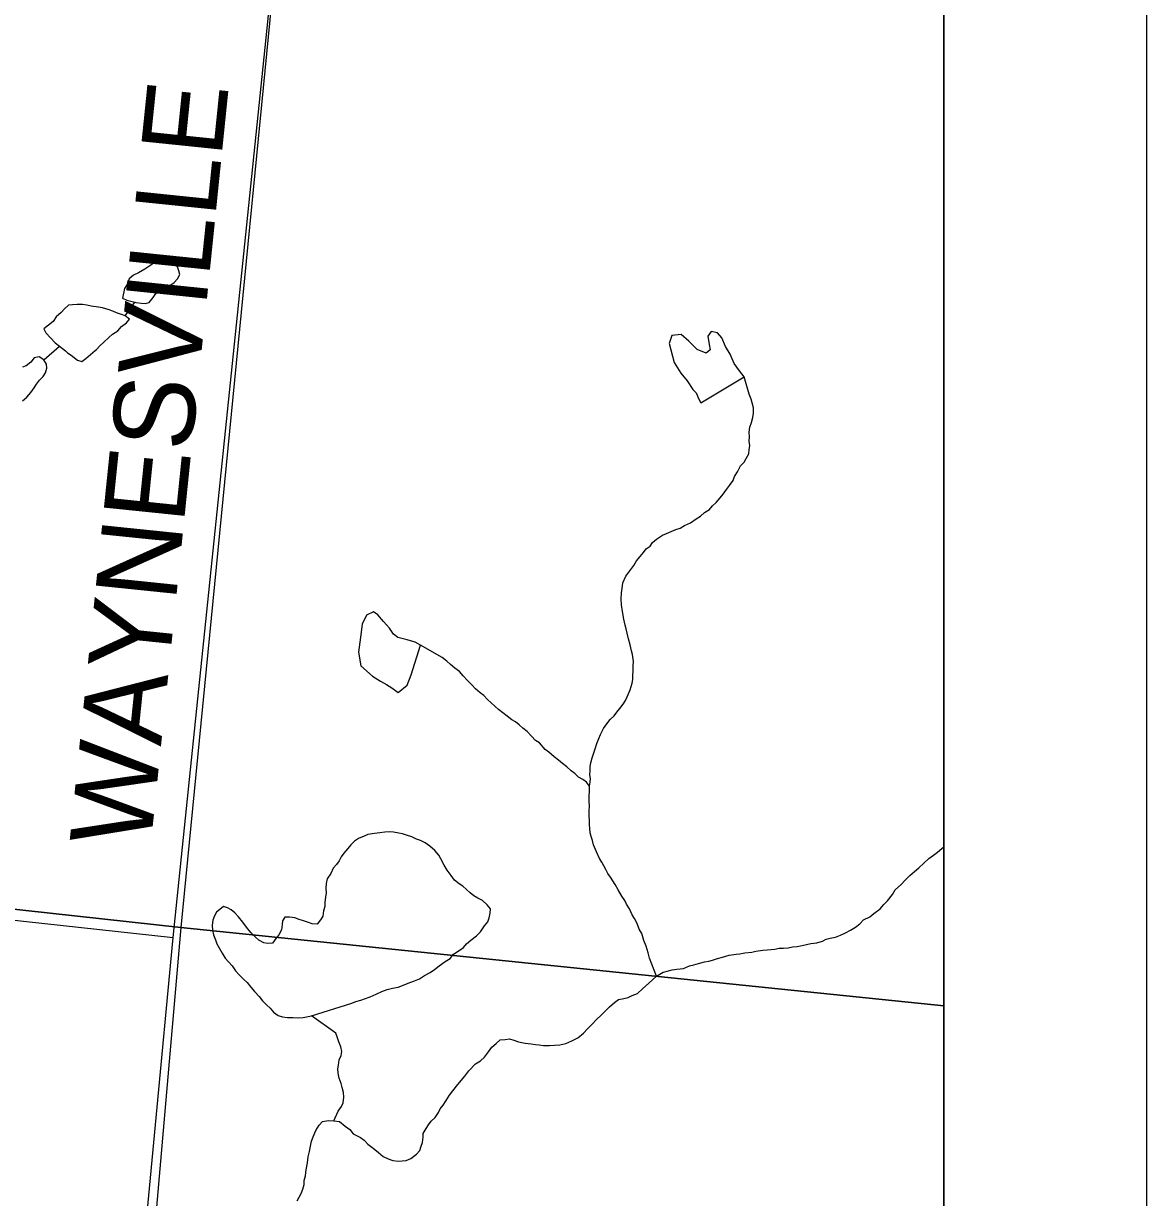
# Model space of a CAD drawing. Extents: x 0 to 34, y -4 to 22.
# Drawn here: x 8.446 to 9, y 18.278 to 18.856 of the extents above; entities that cross this region are included whole.
import ezdxf

# ---------------------------------------------------------------- set-up
doc = ezdxf.new("R2010")
doc.units = 0
for name, color, linetype in [('GM_X_Minor_Lake', 7, 'Continuous'), ('GM_X_Minor_River', 7, 'Continuous'), ('GM_X_Section', 7, 'Continuous'), ('GM_X_Township', 7, 'Continuous'), ('GM_X_Township_Road', 7, 'Continuous'), ('GM_X_Township_Road_Text', 7, 'Continuous'), ('SH_Data', 7, 'Continuous'), ('SN_P_Text', 7, 'Continuous')]:
    doc.layers.add(name, color=color, linetype=linetype)

msp = doc.modelspace()

# ---------------------------------------------------------------- linework, layer by layer
at = {"layer": 'GM_X_Minor_Lake'}
msp.add_line((8.54502, 18.42137), (8.54145, 18.41854), dxfattribs=at)
for points in [[(8.50129, 18.71911), (8.50181, 18.71896), (8.50448, 18.71861), (8.50635, 18.71855), (8.50824, 18.71903), (8.5102, 18.72137), (8.51161, 18.72347), (8.51381, 18.72527), (8.51572, 18.72628), (8.51843, 18.72726), (8.52062, 18.7288), (8.52229, 18.73062), (8.52343, 18.73272), (8.52296, 18.7346), (8.52222, 18.7365), (8.52042, 18.73896), (8.51891, 18.74168), (8.5165, 18.74175), (8.5146, 18.74101), (8.51159, 18.73923), (8.50912, 18.73744), (8.50611, 18.73539), (8.5031, 18.73361), (8.50065, 18.73236), (8.49845, 18.73055), (8.49756, 18.72818), (8.49615, 18.72582), (8.49518, 18.72104)], [(8.49518, 18.72104), (8.4973, 18.72017), (8.50129, 18.71911)], [(8.48176, 18.69529), (8.48229, 18.69579), (8.48396, 18.69761), (8.4859, 18.69942), (8.48838, 18.70175), (8.49031, 18.70329), (8.49278, 18.70508), (8.49473, 18.70716), (8.4972, 18.70895), (8.49859, 18.71078), (8.49651, 18.71245), (8.49465, 18.71304), (8.49227, 18.71391), (8.49042, 18.71477), (8.48857, 18.71536), (8.48538, 18.71626), (8.48325, 18.7166), (8.47979, 18.71724), (8.47765, 18.71757), (8.47552, 18.7179), (8.47285, 18.71799), (8.47043, 18.71779), (8.46855, 18.71759), (8.46661, 18.71578), (8.46494, 18.71396), (8.46247, 18.7119), (8.46105, 18.70954), (8.45637, 18.70594)], [(8.45637, 18.70594), (8.45738, 18.70404), (8.45971, 18.70156), (8.46204, 18.69909), (8.46413, 18.69742), (8.46698, 18.69508)], [(8.44582, 18.67047), (8.44803, 18.67227), (8.44998, 18.67462), (8.45167, 18.67697), (8.4528, 18.6788), (8.4542, 18.68063), (8.45613, 18.68244), (8.45727, 18.68427), (8.45788, 18.68666), (8.45767, 18.68854), (8.45641, 18.69071), (8.45404, 18.69212), (8.45161, 18.69166), (8.44994, 18.68958), (8.44774, 18.68777), (8.44584, 18.68703)], [(8.46698, 18.69508), (8.46804, 18.69409), (8.46988, 18.69297), (8.47301, 18.69047), (8.47513, 18.68987), (8.47706, 18.69141), (8.48176, 18.69529)], [(8.62565, 18.38041), (8.62835, 18.38113), (8.63105, 18.38158), (8.63404, 18.38282), (8.63594, 18.38357), (8.63919, 18.3848), (8.64163, 18.38579), (8.6441, 18.38732), (8.64683, 18.38884), (8.64902, 18.39038), (8.65122, 18.39218), (8.65424, 18.39422), (8.6567, 18.39575), (8.65838, 18.39783), (8.66057, 18.39937), (8.66331, 18.40115), (8.66471, 18.40298), (8.66691, 18.40478), (8.66966, 18.40684), (8.6716, 18.40891), (8.67357, 18.41179), (8.67525, 18.41388), (8.67585, 18.41573), (8.67646, 18.41811), (8.67653, 18.42025), (8.67499, 18.42216), (8.67265, 18.42437), (8.67028, 18.42552), (8.66844, 18.42664), (8.66661, 18.42803), (8.66479, 18.42969), (8.66297, 18.43135), (8.66113, 18.43248), (8.65878, 18.43442), (8.65725, 18.4366), (8.65519, 18.43934), (8.65367, 18.44179), (8.65216, 18.44478), (8.65115, 18.44668), (8.64908, 18.44888), (8.64674, 18.45109), (8.64439, 18.45276), (8.64201, 18.4539), (8.64016, 18.4545), (8.63778, 18.45564), (8.63513, 18.45652), (8.63328, 18.45711), (8.63141, 18.45744), (8.62875, 18.45805), (8.62688, 18.45811), (8.62446, 18.45792), (8.62204, 18.45773), (8.61935, 18.45728), (8.61612, 18.45684), (8.61422, 18.4561), (8.6115, 18.45485), (8.60958, 18.45357), (8.60765, 18.45176), (8.60625, 18.44993), (8.60429, 18.44759), (8.60289, 18.44576), (8.60203, 18.44392), (8.60063, 18.44209), (8.59896, 18.44027), (8.5978, 18.43764), (8.59611, 18.43502), (8.5955, 18.43263), (8.59542, 18.43023), (8.59561, 18.42809), (8.59528, 18.42596), (8.59493, 18.42357), (8.59486, 18.42143), (8.59425, 18.41931), (8.5939, 18.41666), (8.59276, 18.41482), (8.59109, 18.41273), (8.58868, 18.41281), (8.58682, 18.4134), (8.58444, 18.41428), (8.58232, 18.41488), (8.5802, 18.41574), (8.57753, 18.41609), (8.57513, 18.41617), (8.57399, 18.41433), (8.57393, 18.41246), (8.57358, 18.4098), (8.57216, 18.40744), (8.57076, 18.40561), (8.56907, 18.40326), (8.56666, 18.40307), (8.56479, 18.40339), (8.56243, 18.4048), (8.56061, 18.40646), (8.55853, 18.4084), (8.55673, 18.41059), (8.55441, 18.4136), (8.55236, 18.41633), (8.55055, 18.41826), (8.54872, 18.41965), (8.54688, 18.42078), (8.54502, 18.42137)], [(8.54145, 18.41854), (8.54058, 18.4167), (8.53971, 18.41459), (8.53936, 18.41219), (8.53955, 18.40978), (8.54001, 18.40737), (8.541, 18.40493), (8.54174, 18.40304), (8.543, 18.4006), (8.54427, 18.39842), (8.54579, 18.39597), (8.54734, 18.39405), (8.54915, 18.39212), (8.55094, 18.38966), (8.55275, 18.38774), (8.55482, 18.38554), (8.55665, 18.38388), (8.55845, 18.38168), (8.56025, 18.37949), (8.56258, 18.37702), (8.56412, 18.37483), (8.5662, 18.3729), (8.56802, 18.37124), (8.56956, 18.36932), (8.57192, 18.36765), (8.57404, 18.36705), (8.57644, 18.3667), (8.57912, 18.36662), (8.58179, 18.36654), (8.58421, 18.36673), (8.58664, 18.36719), (8.58831, 18.36755)], [(8.58831, 18.36755), (8.60829, 18.37374), (8.61019, 18.37448), (8.61262, 18.3752), (8.61452, 18.37595), (8.61723, 18.37693), (8.62022, 18.37818), (8.62294, 18.37943), (8.62565, 18.38041)]]:
    msp.add_lwpolyline(points, dxfattribs=at)
at = {"layer": 'GM_X_Minor_River'}
for points in [[(8.49651, 18.71245), (8.50129, 18.71911)], [(8.80171, 18.68236), (8.79937, 18.68535), (8.79678, 18.68889), (8.79474, 18.69349), (8.79243, 18.69729), (8.79066, 18.70161), (8.78857, 18.70407), (8.78538, 18.70468), (8.78371, 18.70232), (8.78442, 18.69829), (8.78489, 18.6956), (8.78297, 18.69404), (8.77846, 18.69576), (8.77428, 18.69987), (8.77061, 18.70317), (8.76604, 18.70274), (8.76461, 18.69877), (8.76706, 18.68935), (8.77041, 18.68419), (8.77353, 18.68037), (8.77637, 18.67602), (8.77794, 18.67438), (8.77921, 18.6714), (8.78023, 18.66951)], [(8.45641, 18.69071), (8.46413, 18.69742)], [(8.78023, 18.66951), (8.80171, 18.68236)], [(8.78457, 18.617), (8.78597, 18.61882), (8.7879, 18.62037), (8.78985, 18.62271), (8.79125, 18.62454), (8.79293, 18.62689), (8.79433, 18.62872), (8.79629, 18.63133), (8.79689, 18.63318), (8.79831, 18.63554), (8.79975, 18.63844), (8.80168, 18.64025), (8.80255, 18.64209), (8.80396, 18.64445), (8.80402, 18.64632), (8.80436, 18.64844), (8.80417, 18.65059), (8.80424, 18.65272), (8.80405, 18.65513), (8.80439, 18.65753), (8.80528, 18.6599), (8.80589, 18.66229), (8.80623, 18.66442), (8.80632, 18.66708), (8.80559, 18.66951), (8.80512, 18.6714), (8.80413, 18.67383), (8.80171, 18.68236)], [(8.75848, 18.387), (8.75503, 18.39592), (8.75431, 18.39861), (8.75335, 18.40185), (8.7521, 18.40456), (8.75114, 18.40806), (8.74987, 18.41024), (8.74889, 18.41294), (8.74763, 18.41538), (8.74636, 18.41729), (8.74512, 18.42027), (8.74358, 18.42245), (8.74284, 18.42434), (8.7413, 18.42653), (8.73953, 18.42952), (8.73801, 18.43224), (8.73572, 18.43578), (8.73444, 18.43769), (8.73343, 18.43959), (8.7314, 18.44313), (8.73039, 18.44503), (8.7289, 18.44828), (8.7274, 18.4518), (8.72694, 18.45395), (8.7262, 18.45584), (8.72573, 18.45773), (8.72553, 18.45987), (8.72532, 18.46175), (8.72538, 18.46362), (8.7252, 18.46603), (8.72527, 18.46843), (8.72535, 18.47083), (8.72517, 18.47324), (8.72525, 18.47564), (8.72533, 18.47831), (8.72541, 18.48071), (8.72574, 18.48257), (8.7258, 18.48444), (8.7256, 18.48632), (8.72566, 18.48819), (8.72573, 18.49032), (8.72606, 18.49218), (8.72667, 18.49457), (8.72816, 18.49906), (8.72905, 18.50171), (8.72993, 18.50408), (8.73081, 18.50619), (8.73225, 18.50909), (8.73393, 18.51144), (8.73561, 18.51352), (8.73754, 18.51534), (8.73894, 18.51716), (8.74034, 18.51899), (8.74202, 18.52107), (8.74315, 18.52291), (8.74401, 18.52475), (8.74547, 18.52818), (8.74637, 18.53136), (8.7467, 18.53322), (8.74677, 18.53509), (8.74685, 18.53749), (8.74693, 18.53989), (8.747, 18.54202), (8.74657, 18.54551), (8.7461, 18.5474), (8.7454, 18.55035), (8.74469, 18.55332), (8.74398, 18.55601), (8.74351, 18.55816), (8.74304, 18.56004), (8.74233, 18.563), (8.74165, 18.56677), (8.74122, 18.56998), (8.74105, 18.57293), (8.74115, 18.57586), (8.74149, 18.57799), (8.74185, 18.58092), (8.7433, 18.58408), (8.74526, 18.58669), (8.74722, 18.5893), (8.74864, 18.59166), (8.75031, 18.59375), (8.75199, 18.59583), (8.75339, 18.59766), (8.75531, 18.59894), (8.75644, 18.60077), (8.75837, 18.60231), (8.76138, 18.60436), (8.76328, 18.6051), (8.76572, 18.60609), (8.7679, 18.6071), (8.77007, 18.60783), (8.77225, 18.6091), (8.77524, 18.61034), (8.77799, 18.61239), (8.78017, 18.61366), (8.78211, 18.61547), (8.78457, 18.617)], [(8.64207, 18.55013), (8.63942, 18.55153), (8.63543, 18.5527), (8.63091, 18.55388), (8.62881, 18.55553), (8.62673, 18.55852), (8.62387, 18.5618), (8.621, 18.56508), (8.61889, 18.56647), (8.61538, 18.56495), (8.61339, 18.56045), (8.61243, 18.55406), (8.61145, 18.5466), (8.61262, 18.53988), (8.61839, 18.53493), (8.62235, 18.53243), (8.62525, 18.53075), (8.62789, 18.52908)], [(8.62789, 18.52908), (8.63105, 18.52687), (8.63543, 18.5305), (8.63742, 18.53554), (8.64207, 18.55013)], [(8.72541, 18.48071), (8.72387, 18.48263), (8.72204, 18.48402), (8.71993, 18.48516), (8.71811, 18.48682), (8.71628, 18.48821), (8.7142, 18.49014), (8.71212, 18.49181), (8.71003, 18.49348), (8.70794, 18.49514), (8.70533, 18.49736), (8.70351, 18.49876), (8.70067, 18.50205), (8.69883, 18.50317), (8.69676, 18.50537), (8.69469, 18.50758), (8.6926, 18.50924), (8.69078, 18.5109), (8.68895, 18.51229), (8.68711, 18.51342), (8.68475, 18.5151), (8.68267, 18.51676), (8.68058, 18.51843), (8.67876, 18.52009), (8.67694, 18.52175), (8.67512, 18.52341), (8.67331, 18.52533), (8.67148, 18.52672), (8.66913, 18.52867), (8.66732, 18.53059), (8.66525, 18.53279), (8.66318, 18.535), (8.66137, 18.53719), (8.65902, 18.53886), (8.65693, 18.54053), (8.65511, 18.54219), (8.65276, 18.54413), (8.64207, 18.55013)], [(8.83753, 18.40352), (8.84023, 18.40424), (8.84214, 18.40525), (8.84403, 18.40572), (8.84672, 18.40618), (8.84917, 18.40717), (8.85162, 18.40843), (8.85407, 18.40969), (8.85653, 18.41122), (8.85873, 18.41275), (8.86041, 18.41484), (8.86367, 18.41634), (8.8656, 18.41788), (8.86862, 18.42019), (8.87056, 18.42227), (8.87223, 18.42409), (8.87475, 18.42722), (8.87616, 18.42958), (8.8792, 18.43242), (8.88087, 18.43424), (8.88336, 18.43657), (8.88557, 18.43864), (8.88777, 18.44044), (8.89026, 18.44276), (8.89275, 18.44509), (8.89494, 18.44663), (8.89687, 18.44817), (8.89907, 18.44997), (8.9, 18.45084)], [(8.61436, 18.30623), (8.61617, 18.3043), (8.61879, 18.30235), (8.62139, 18.30013), (8.62374, 18.29819), (8.62611, 18.29705), (8.62849, 18.29617), (8.63116, 18.29582), (8.63304, 18.29603), (8.63493, 18.29624), (8.63737, 18.29724), (8.64012, 18.29929), (8.64178, 18.30111), (8.64239, 18.30322), (8.64299, 18.30508), (8.64334, 18.30774), (8.64341, 18.3096), (8.64482, 18.31197), (8.64595, 18.3138), (8.64735, 18.31563), (8.64929, 18.31744), (8.65097, 18.31979), (8.65184, 18.32163), (8.65324, 18.32346), (8.65466, 18.32582), (8.65635, 18.32844), (8.65803, 18.33052), (8.66054, 18.33365), (8.66389, 18.33782), (8.66586, 18.34044), (8.66918, 18.3438), (8.67164, 18.34533), (8.67358, 18.34714), (8.67554, 18.34975), (8.67723, 18.3521), (8.67943, 18.35391), (8.68136, 18.35572), (8.68378, 18.35591), (8.68593, 18.35611), (8.68805, 18.35551), (8.69044, 18.35464), (8.69363, 18.354), (8.69657, 18.35364), (8.6987, 18.35331), (8.70057, 18.35325), (8.7027, 18.35292), (8.70565, 18.35283), (8.70807, 18.35302), (8.71075, 18.35321), (8.71372, 18.35392), (8.71671, 18.35516), (8.71971, 18.35667), (8.72246, 18.35899), (8.72441, 18.36107), (8.72663, 18.3634), (8.72885, 18.36574), (8.73106, 18.36781), (8.73327, 18.36988), (8.73521, 18.37195), (8.73769, 18.37401), (8.73962, 18.37556), (8.74231, 18.37601), (8.74447, 18.37647), (8.74638, 18.37748), (8.74909, 18.37847), (8.75158, 18.3808), (8.75462, 18.38364), (8.75656, 18.38545), (8.75848, 18.387), (8.76177, 18.38903), (8.76366, 18.38951), (8.76609, 18.39023), (8.76851, 18.39043), (8.77174, 18.39086), (8.77473, 18.3921), (8.77689, 18.39257), (8.77905, 18.3933), (8.78202, 18.39402), (8.78418, 18.39448), (8.78607, 18.39496), (8.78851, 18.39568), (8.79094, 18.39641), (8.79419, 18.39738), (8.79769, 18.39781), (8.79957, 18.39802), (8.802, 18.39847), (8.80549, 18.3989), (8.80738, 18.39938), (8.81088, 18.3998), (8.81303, 18.4), (8.81491, 18.40021), (8.81679, 18.40042), (8.81895, 18.40089), (8.82109, 18.40082), (8.82325, 18.40102), (8.8254, 18.40149), (8.82782, 18.40168), (8.83025, 18.40214), (8.83241, 18.40261), (8.83457, 18.40308), (8.83753, 18.40352)], [(8.5994, 18.31577), (8.60144, 18.32052), (8.60312, 18.32287), (8.60399, 18.32471), (8.60434, 18.32737), (8.60415, 18.32978), (8.60343, 18.33221), (8.60296, 18.3341), (8.60197, 18.3368), (8.60152, 18.33922), (8.60132, 18.34136), (8.60165, 18.34322), (8.60201, 18.34588), (8.60288, 18.34799), (8.60321, 18.34985), (8.60275, 18.35227), (8.60176, 18.3547), (8.60104, 18.35713), (8.6003, 18.35902), (8.58831, 18.36755)], [(8.58122, 18.27626), (8.58322, 18.27994), (8.58409, 18.28205), (8.58471, 18.28444), (8.58477, 18.2863), (8.58538, 18.28869), (8.58575, 18.29162), (8.5864, 18.29507), (8.58676, 18.298), (8.58738, 18.30065), (8.58771, 18.30251), (8.58835, 18.3057), (8.58923, 18.30781), (8.5904, 18.31098), (8.5921, 18.31359), (8.59377, 18.31541), (8.59673, 18.31585), (8.5994, 18.31577), (8.60207, 18.31542), (8.60495, 18.3132), (8.6073, 18.31152), (8.60883, 18.30934), (8.61253, 18.30762), (8.61436, 18.30623)]]:
    msp.add_lwpolyline(points, dxfattribs=at)
at = {"layer": 'GM_X_Section'}
for points in [[(7.90105, 19.1654), (8.59171, 19.1029), (8.52385, 18.41099), (7.82864, 18.48717)], [(8.9, 18.37244), (8.9, 19.07415), (8.59171, 19.1029), (8.52385, 18.41099)], [(7.82864, 18.48717), (8.52385, 18.41099), (8.46166, 17.69579), (7.74884, 17.75662)], [(8.9, 17.65526), (8.9, 18.37244), (8.52385, 18.41099), (8.46166, 17.69579)]]:
    msp.add_lwpolyline(points, close=True, dxfattribs=at)
at = {"layer": 'GM_X_Township'}
msp.add_lwpolyline([(8.9, 14.99227), (8.9, 19.07101), (8.74356, 19.08501), (8.61662, 19.09679), (7.89749, 19.16191), (7.8558, 18.75422), (7.82296, 18.48336), (7.70395, 17.41086)], dxfattribs=at)
at = {"layer": 'GM_X_Township_Road'}
for points in [[(8.47404, 18.05544), (8.47406, 18.05668), (8.47447, 18.08008), (8.47676, 18.10332), (8.48054, 18.12066), (8.48577, 18.14385), (8.48961, 18.16466), (8.49094, 18.17909), (8.49418, 18.1959), (8.49862, 18.20465), (8.50266, 18.22144), (8.52009, 18.40608), (8.59186, 19.09904), (8.59311, 19.11604)], [(7.98156, 18.4659), (7.98607, 18.4654), (8.23528, 18.43711), (8.52009, 18.40608)]]:
    msp.add_lwpolyline(points, dxfattribs=at)
at = {"layer": 'SH_Data'}
for p, q in [((9, 21), (9, 14)), ((8.9, 20.9), (8.9, 14.1))]:
    msp.add_line(p, q, dxfattribs=at)
at = {"layer": 'SN_P_Text'}
msp.add_lwpolyline([(8.9, 14.1), (8.9, 20.9), (2.1, 20.9), (2.1, 14.1)], close=True, dxfattribs=at)

# ---------------------------------------------------------------- texts
at = {"layer": 'GM_X_Township_Road_Text'}
msp.add_text('WAYNESVILLE', height=0.04, rotation=84.12672, dxfattribs=at).set_placement((8.50893, 18.44984))

doc.saveas('drawing.dxf')
